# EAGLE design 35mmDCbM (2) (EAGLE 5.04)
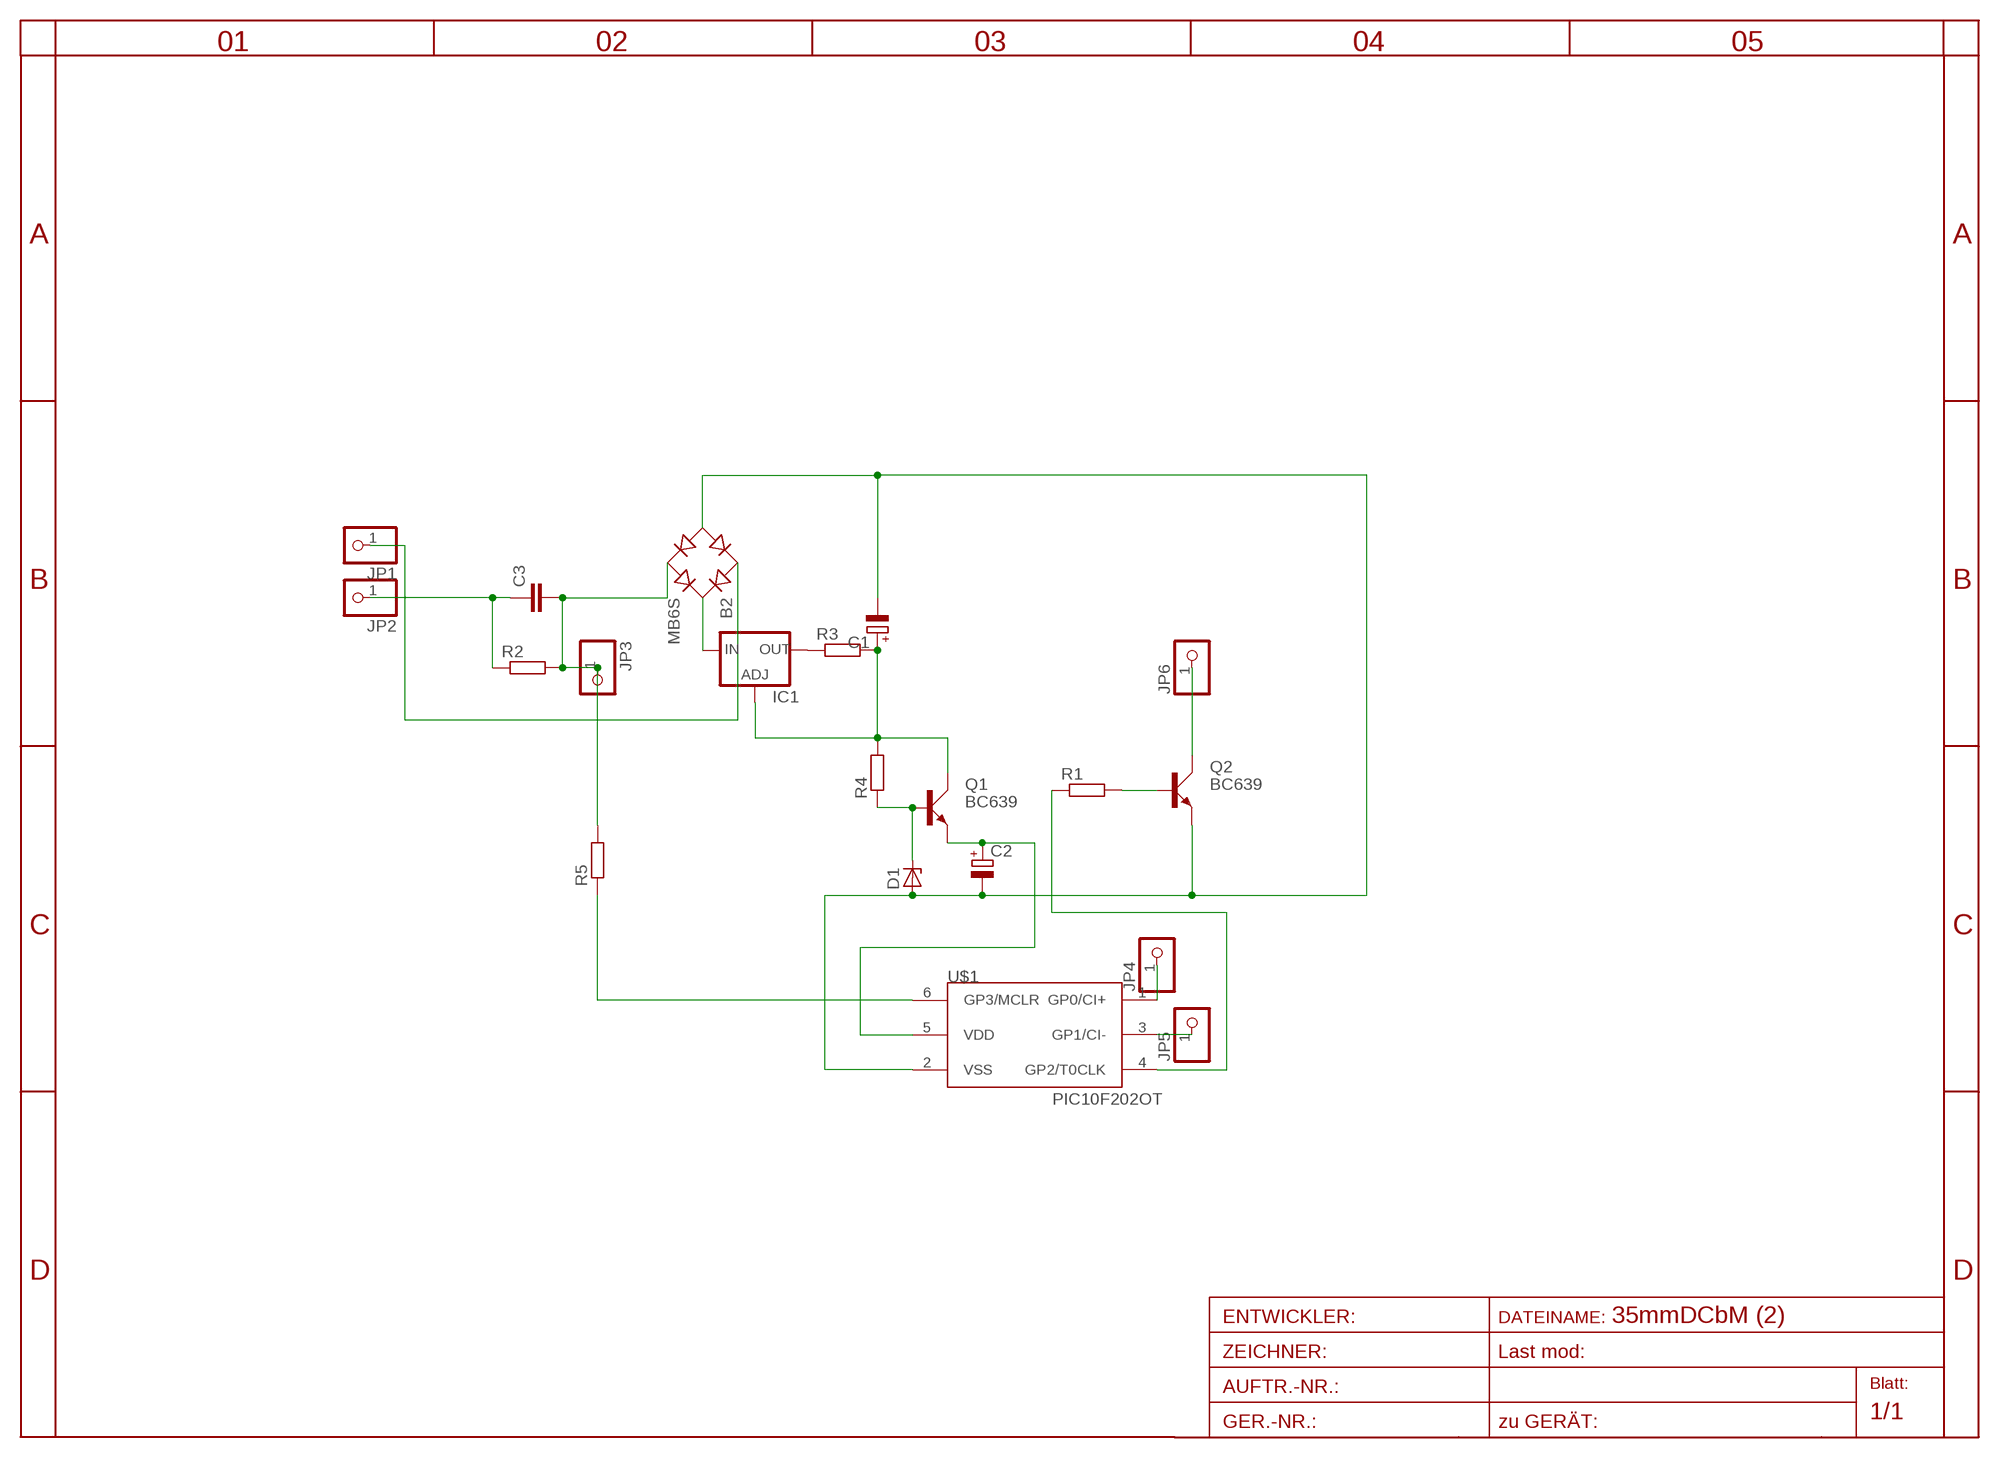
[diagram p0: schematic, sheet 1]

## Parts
B2  MB6S  [SOIC-4]
C1  CPOL-EUE5-8.5  [E5-8,5]
C2  CPOL-EUE2.5-6  [E2,5-6]
C3  C-EU102-064X133  [C102-064X133]
D1  ZENER-DIODESOT23  [SOT23]
IC1  LM317LZ  [317L]
JP1  PINHD-1X1  [1X01]
JP2  PINHD-1X1  [1X01]
JP3  PINHD-1X1  [1X01]
JP4  PINHD-1X1  [1X01]
JP5  PINHD-1X1  [1X01]
JP6  PINHD-1X1  [1X01]
Q1  BC639  [SOT54D]
Q2  BC639  [SOT54D]
R1  R-EU_R1206  [R1206]
R2  R-EU_R1206  [R1206]
R3  R-EU_R1206  [R1206]
R4  R-EU_R1206  [R1206]
R5  R-EU_R1206  [R1206]
U$1  PIC10F202OT  [SOT23-6]

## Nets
AC: B2.~1(AC1) JP1.1
AC+: C3.1 JP2.1 R2.1
N$1: B2.~2(AC2) C3.2 JP3.1 R2.2 R5.2
N$2: B2.+ IC1.3(IN)
N$3: R5.1 U$1.6(GP3/MCLR)
N$4: C1.+ IC1.1(ADJ) Q1.C R3.2 R4.2
N$5: IC1.2(OUT) R3.1
N$6: D1.3(C) Q1.B R4.1
N$8: Q2.B R1.2
N$9: B2.- C1.- C2.- D1.1(A) Q2.E U$1.2(VSS)
N$10: C2.+ Q1.E U$1.5(VDD)
N$11: R1.1 U$1.4(GP2/T0CLK)
N$12: JP4.1 U$1.1(GP0/CI+)
N$13: JP5.1 U$1.3(GP1/CI-)
N$14: JP6.1 Q2.C

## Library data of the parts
B2 = rectifier:MB*S: Bridge Rectifier Source: http://www.fairchildsemi.com/ds/MB/MB6S.pdf
C1 = rcl-2:CPOL-EU: POLARIZED CAPACITOR, European symbol
C2 = rcl:CPOL-EU: POLARIZED CAPACITOR, European symbol
C3 = rcl:C-EU: CAPACITOR, European symbol
D1 = diode-1:ZENER-DIODE: Z-Diode
IC1 = v-reg-3:LM317L: Adjustable Voltage Regulator, 1.2V to 37V, 100mA
JP1-JP6 = pinhead:PINHD-1X1: PIN HEADER
Q1 Q2 = transistor-small-signal:BC639: NPN TRANSISTOR
R1-R5 = rcl:R-EU_: RESISTOR, European symbol
U$1 = microchip-5:PIC10F2*: uPC nW 0,25/0,5k Program Flash memory Comparator

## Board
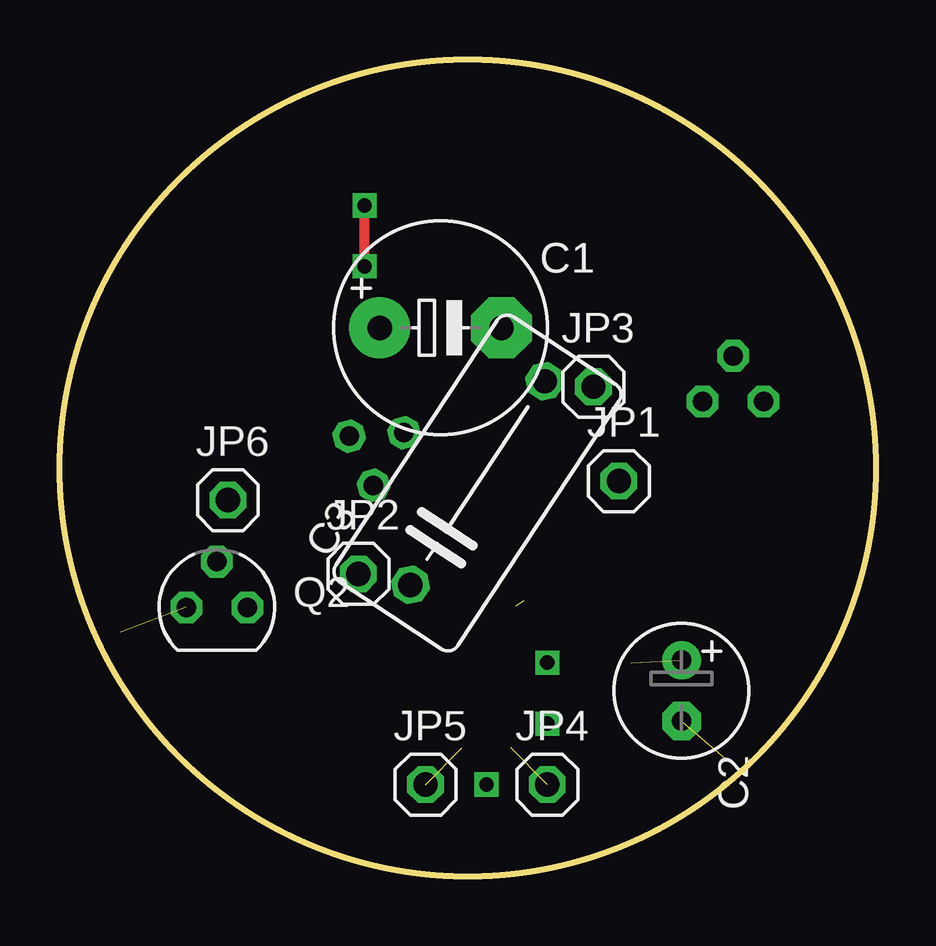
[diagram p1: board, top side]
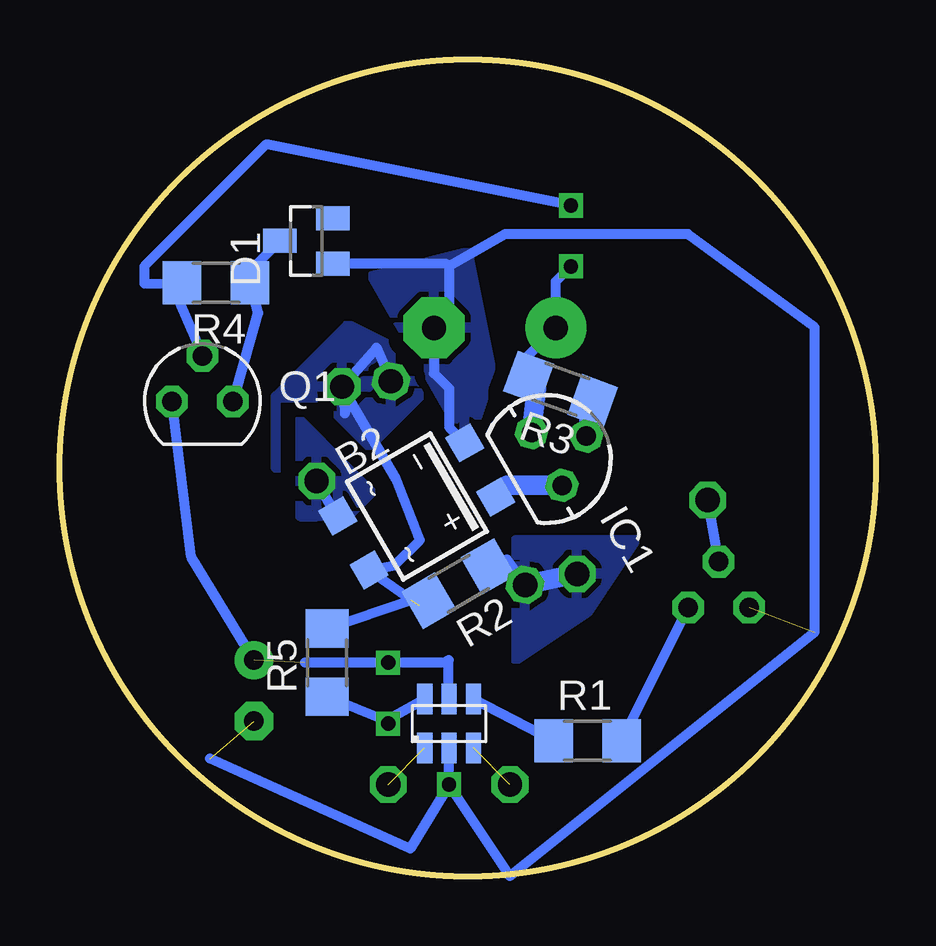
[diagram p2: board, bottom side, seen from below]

Size 34 x 34 mm. Coordinates in mm from the lower left corner, seen from the top.
Outline: circle at 17,17 radius 17
Copper layers (1*16): Top 0.035mm / dielectric 1.5mm / Bottom 0.035mm
Design rules "default *": minimum track width 10mil, minimum drill 24mil, track to track 8mil, track to pad 8mil, pad to pad 8mil, via to via 8mil, smd to smd 8mil, copper to edge 4mil, drill to drill 8mil, minimum pad ring 10mil, minimum via ring 8mil, stop-mask expansion 4mil, vias tented up to drill 0mil, thermal gap 10mil

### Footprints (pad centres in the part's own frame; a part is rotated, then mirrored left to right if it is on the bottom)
SOIC-4 = smd 1.2 x 1.2: + 1.3,3.05; - -1.3,3.05; ~1 -1.3,-3.05; ~2 1.3,-3.05
E5-8,5 = drill 1.016 pad 2.54 round: + -2.54,0 | drill 1.016 pad 2.54 octagon: - 2.54,0
E2,5-6 = drill 0.813 pad 1.6 round: + -1.27,0 | drill 0.813 pad 1.6 octagon: - 1.27,0
C102-064X133 = drill 1.016 octagon: 1 -5.08,0; 2 5.08,0
SOT23 = smd 1 x 1.4: 1 -0.95,-1.1; 2 0.95,-1.1; 3 0,1.1
317L = drill 0.813 octagon: 1 -1.27,0; 2 0,1.905; 3 1.27,0
1X01 = drill 1.016 octagon: 1 0,0
SOT54D = drill 0.813 octagon: B 1.27,0; C 0,1.905; E -1.27,0
R1206 = smd 1.6 x 1.803: 1 -1.422,0; 2 1.422,0
SOT23-6 = smd 0.635 x 1.27: 1 -1.016,-1.016; 2 0,-1.016; 3 1.016,-1.016; 4 1.016,1.016; 5 0,1.016; 6 -1.016,1.016

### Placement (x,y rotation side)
B2  19.12,15.4 300 bottom
C1  15.87,22.84 0 top
C2  25.91,7.72 270 top
C3  17.41,16.37 56.6 top
D1  23.73,26.46 90 bottom
IC1  13.71,17.37 300 bottom
JP1  23.3,16.46 0 top
JP2  12.45,12.59 0 top
JP3  22.24,20.39 0 top
JP4  20.32,3.81 0 top
JP5  15.24,3.81 0 top
JP6  7,15.66 0 top
Q1  28.06,19.77 0 bottom
Q2  6.54,11.19 0 top
R1  12,5.64 0 bottom
R2  17.39,12.18 210 bottom
R3  13.13,20.29 160 bottom
R4  27.5,24.72 180 bottom
R5  22.86,8.89 90 bottom
U$1  17.78,6.35 0 bottom

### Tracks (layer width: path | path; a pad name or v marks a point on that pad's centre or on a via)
AC
  Bottom 0.406: B2.~1 22.44,15 JP1.1
  pour Bottom (isolate 0.61): 21,16 24,19 24,15 22,15
AC+
  Bottom 0.406: R2.1 15.35,13.19 C3.1
  Bottom 0.813: JP2.1 C3.1
  pour Bottom (isolate 0.61): 10,14 15,14 15,9 12,11
N$1  (1 unrouted)
  Bottom 0.406: C3.2 20.81,22.01 JP3.1 | JP3.1 22.12,19.27 | R2.2 19.02,11.25 B2.~2 20.05,12.95 19,14 20,16.55 JP3.1 | 19.36,11.5 R5.2
  pour Bottom (isolate 0.61, rank 2): 20,22 19,20 22,17 25,17 25,20 22,23
N$2
  Bottom 0.406: IC1.3 13.36,16.39 | 15.36,16.27 B2.+
  Bottom 0.813: IC1.3 15.36,16.27
N$3
  Bottom 0.406: U$1.6 20.4,6.46 R5.1
N$4  (via drill 0.6)
  Top 0.406: v12.7,25.4 v12.7,27.94
  Bottom 0.406: 14.14,20.32 R3.2 14.46,21.7 C1.+ 13.33,24.77 v12.7,25.4 | Q1.C 29.12,24.11 R4.2 30.48,24.68 30.48,25.4 25.4,30.48 v12.7,27.94
  Bottom 0.813: IC1.1 14.14,20.32
N$5
  Bottom 0.406: R3.1 11.86,19.39
  Bottom 0.813: 11.86,19.39 IC1.2
N$6
  Bottom 0.406: D1.3 26.68,24.61 R4.1 25.73,23.47 Q1.B
N$7  (via drill 0.6)
  other vias: 20.32,8.89
N$8
  Bottom 0.406: R1.2 Q2.B
N$9  (via drill 0.6)  (2 unrouted)
  Bottom 0.406: v17.78,3.81 15.24,0 2.54,10.16 2.54,22.86 7.82,26.74 15.44,26.74 17.78,25.4 | 27.75,4.89 19.4,1.14 v17.78,3.81 | v17.78,3.81 U$1.2 | D1.1 17.89,25.51 17.78,25.4 | 17.78,25.4 17.78,23.46 C1.- 18.41,20.95 17.78,20.32 17.78,18.7 B2.-
  pour Bottom (isolate 0.61, rank 2): 16,21 17,26 21,25 17,18
N$10  (1 unrouted)
  Bottom 0.406: Q1.E 28.53,13.3 C2.+ | 23.8,8.89 18,8.89 17.8,9 17.8,7.39 U$1.5
N$11
  Bottom 0.406: R1.1 U$1.4
N$12  (1 unrouted)
N$13  (1 unrouted)
N$14
  Bottom 0.406: Q2.C JP6.1
N$15  (via drill 0.6)
  other vias: 20.32,6.35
